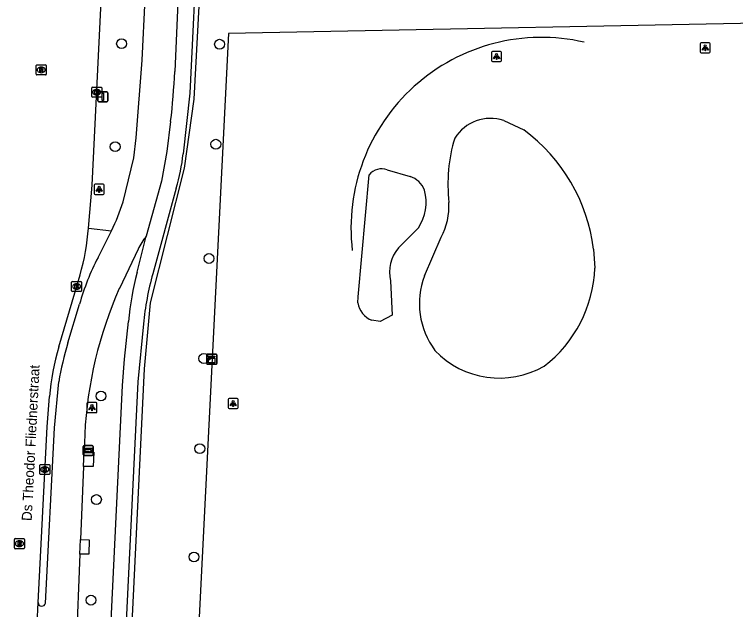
# Model space of a CAD drawing. Extents: x 161761 to 162722, y 384793 to 385405.
# Drawn here: x 162129 to 162200.7, y 385280.9 to 385340.1 of the extents above; entities that cross this region are included whole.
import ezdxf

# ---------------------------------------------------------------- set-up
doc = ezdxf.new("R2010")
doc.units = 0
for name, color, linetype in [('IMGEO_Berm_groen', 7, 'Continuous'), ('IMGEO_Boom', 7, 'Continuous'), ('IMGEO_Fietspad_gesloten', 7, 'Continuous'), ('IMGEO_Groenvoorziening', 7, 'Continuous'), ('IMGEO_Hek', 7, 'Continuous'), ('IMGEO_Kast', 7, 'Continuous'), ('IMGEO_Kolk', 7, 'Continuous'), ('IMGEO_Lichtpunt', 7, 'Continuous'), ('IMGEO_Openbare_ruimte_label', 7, 'Continuous'), ('IMGEO_Rijbaan_lokaal_gesloten', 7, 'Continuous'), ('IMGEO_Rioolput', 7, 'Continuous'), ('IMGEO_Verkeersbordpaal', 7, 'Continuous'), ('IMGEO_Verkeerseiland_open', 7, 'Continuous'), ('IMGEO_Voetpad_open', 7, 'Continuous'), ('IMGEO_Wegwijzer', 7, 'Continuous')]:
    doc.layers.add(name, color=color, linetype=linetype)

msp = doc.modelspace()

# ---------------------------------------------------------------- linework, layer by layer
at = {"layer": 'IMGEO_Berm_groen'}
for points in [[(162135.902, 385296.656), (162136.872, 385296.597), (162136.811, 385295.159), (162135.843, 385295.176)], [(162135.553, 385287.905), (162136.417, 385287.87), (162136.38, 385286.457), (162135.496, 385286.459)]]:
    msp.add_lwpolyline(points, dxfattribs=at)
at = {"layer": 'IMGEO_Boom'}
for centre in [(162139.634, 385337.193), (162149.378, 385337.145), (162138.998, 385326.956), (162149.005, 385327.204), (162148.319, 385315.843), (162147.806, 385305.902), (162137.589, 385302.172), (162147.413, 385296.939), (162137.138, 385291.878), (162146.832, 385286.174), (162136.595, 385281.876)]:
    msp.add_circle(centre, 0.489, dxfattribs=at)
at = {"layer": 'IMGEO_Fietspad_gesloten'}
for points in [[(162139.783, 385321.485), (162140.845, 385325.839), (162141.092, 385327.83), (162141.672, 385335.573), (162142.271, 385347.778), (162142.207, 385350.248)], [(162145.726, 385349.837), (162145.502, 385347.426), (162144.918, 385334.435)], [(162144.509, 385329.468), (162144.145, 385326.47), (162143.594, 385323.536), (162142.089, 385318.047)], [(162137.294, 385315.952), (162138.638, 385318.607)], [(162141.277, 385316.771), (162139.414, 385312.866)], [(162134.299, 385307.45), (162135.45, 385311.302)], [(162132.066, 385281.578), (162132.954, 385298.991), (162133.395, 385303.575)], [(162135.97, 385298.369), (162135.902, 385296.656)], [(162135.843, 385295.176), (162135.902, 385296.656)], [(162135.843, 385295.176), (162135.553, 385287.905)], [(162135.496, 385286.459), (162135.553, 385287.905)], [(162135.496, 385286.459), (162135.129, 385277.251)]]:
    msp.add_lwpolyline(points, dxfattribs=at)
for centre, radius, start, end in [((162086.015, 385336.785), 58.95, 352.86997, 357.7154), ((162120.972, 385327.302), 19.69, 333.79389, 342.81627), ((162146.167, 385314.556), 5.368, 139.43026, 155.62736), ((162160.039, 385304.242), 25.582, 152.75806, 163.97943), ((162176.927, 385296.297), 41.01, 156.16908, 177.10328), ((162164.556, 385298.348), 31.596, 163.2582, 170.47843), ((162131.708, 385281.644), 0.364, 182.24351, 349.51758)]:
    msp.add_arc(centre, radius, start, end, dxfattribs=at)
at = {"layer": 'IMGEO_Groenvoorziening'}
for points in [[(162399.858, 385354.488), (162376.31, 385353.749), (162286.233, 385352.376), (162211.155, 385350.962), (162211.124, 385352.462), (162147.884, 385351.44), (162146.81, 385331.678), (162145.872, 385324.819), (162142.47, 385311.424), (162141.898, 385304.88), (162139.214, 385249.548), (162133.367, 385130.823)], [(162211.326, 385339.4), (162150.256, 385338.217), (162139.817, 385130.505)], [(162177.62, 385329.568), (162179.614, 385328.627)], [(162166.039, 385324.657), (162168.314, 385323.994)], [(162163.132, 385311.434), (162163.14, 385312.033), (162164.244, 385324.166)], [(162169.135, 385318.896), (162168.204, 385317.932), (162167.159, 385316.892)], [(162169.762, 385314.116), (162171.42, 385317.948)], [(162186.548, 385316.774), (162186.681, 385314.893)], [(162166.353, 385313.631), (162166.541, 385310.198), (162165.325, 385309.574), (162164.511, 385309.697)]]:
    msp.add_lwpolyline(points, dxfattribs=at)
for centre, radius, start, end in [((162176.335, 385325.512), 4.255, 72.4177, 147.3575), ((162169.351, 385314.668), 17.326, 6.98055, 53.67468), ((162187.898, 385323.224), 15.824, 163.16473, 186.54671), ((162165.487, 385323.15), 1.605, 69.87674, 140.71991), ((162167.673, 385321.911), 2.18, 19.15887, 72.89747), ((162165.473, 385321.395), 4.434, 325.69235, 16.12111), ((162165.152, 385321.133), 7.031, 333.06244, 2.33814), ((162170.132, 385314.427), 3.862, 140.34079, 191.89285), ((162173.828, 385315.364), 12.861, 307.35532, 357.89986), ((162176.954, 385311.336), 7.711, 158.86431, 216.85174), ((162165.394, 385311.814), 2.294, 189.53904, 247.35291), ((162177.201, 385312.79), 8.84, 223.44992, 300.07993)]:
    msp.add_arc(centre, radius, start, end, dxfattribs=at)
at = {"layer": 'IMGEO_Hek'}
msp.add_lwpolyline([(162147.884, 385351.44), (162146.81, 385331.678), (162145.872, 385324.819), (162142.47, 385311.424), (162141.898, 385304.88), (162139.214, 385249.548)], dxfattribs=at)
msp.add_arc((162181.402, 385318.855), 18.965, 77.1096, 186.69883, dxfattribs=at)
at = {"layer": 'IMGEO_Kast'}
for p, q in [((162148.172, 385306.327), (162149.013, 385306.327)), ((162149.013, 385306.327), (162148.172, 385306.327)), ((162148.097, 385305.402), (162148.097, 385306.243)), ((162148.097, 385306.243), (162148.097, 385305.402)), ((162149.097, 385306.252), (162149.097, 385305.411)), ((162149.097, 385305.411), (162149.097, 385306.252)), ((162149.022, 385305.327), (162148.181, 385305.327)), ((162148.181, 385305.327), (162149.022, 385305.327))]:
    msp.add_line(p, q, dxfattribs=at)
for points in [[(162148.292, 385306.117), (162148.892, 385306.117), (162148.892, 385306.032), (162148.292, 385306.032), (162148.292, 385306.117)], [(162148.292, 385305.942), (162148.892, 385305.942), (162148.892, 385305.453), (162148.292, 385305.453), (162148.292, 385305.942)]]:
    msp.add_lwpolyline(points, dxfattribs=at)
msp.add_circle((162148.376, 385305.791), 0.0377, dxfattribs=at)
for centre, start, end in [((162148.175, 385306.249), 92.4484, 184.28452), ((162148.175, 385306.249), 92.4484, 184.28452), ((162149.019, 385306.249), 2.4484, 94.28452), ((162149.019, 385306.249), 2.4484, 94.28452), ((162148.175, 385305.405), 182.4484, 274.28452), ((162148.175, 385305.405), 182.4484, 274.28452), ((162149.019, 385305.405), 272.4484, 4.28452), ((162149.019, 385305.405), 272.4484, 4.28452)]:
    msp.add_arc(centre, 0.0779, start, end, dxfattribs=at)
at = {"layer": 'IMGEO_Kolk'}
for p, q in [((162136.742, 385332.875), (162137.594, 385332.875)), ((162136.667, 385331.949), (162136.667, 385332.801)), ((162137.155, 385332.655), (162137.18, 385332.655)), ((162137.668, 385332.801), (162137.668, 385331.949)), ((162137.594, 385331.875), (162136.742, 385331.875)), ((162137.178, 385332.095), (162137.153, 385332.095)), ((162134.742, 385313.557), (162135.594, 385313.557)), ((162134.667, 385312.631), (162134.667, 385313.483)), ((162135.178, 385312.777), (162135.153, 385312.777)), ((162135.155, 385313.337), (162135.18, 385313.337)), ((162135.668, 385313.483), (162135.668, 385312.631)), ((162135.594, 385312.557), (162134.742, 385312.557)), ((162131.507, 385294.441), (162131.507, 385295.293)), ((162131.582, 385295.367), (162132.434, 385295.367)), ((162131.995, 385295.147), (162132.02, 385295.147)), ((162132.508, 385295.293), (162132.508, 385294.441)), ((162132.434, 385294.367), (162131.582, 385294.367)), ((162132.018, 385294.587), (162131.993, 385294.587))]:
    msp.add_line(p, q, dxfattribs=at)
for points in [[(162136.742, 385332.875), (162137.594, 385332.875)], [(162136.667, 385331.949), (162136.667, 385332.801)], [(162136.988, 385332.575), (162137.111, 385332.575), (162137.111, 385332.424), (162137.241, 385332.575), (162137.405, 385332.575), (162137.259, 385332.424), (162137.412, 385332.175), (162137.26, 385332.175), (162137.175, 385332.339), (162137.111, 385332.272), (162137.111, 385332.175), (162136.988, 385332.175), (162136.988, 385332.575)], [(162137.668, 385332.801), (162137.668, 385331.949)], [(162137.594, 385331.875), (162136.742, 385331.875)], [(162134.742, 385313.557), (162135.594, 385313.557)], [(162134.667, 385312.631), (162134.667, 385313.483)], [(162134.988, 385313.257), (162135.111, 385313.257), (162135.111, 385313.106), (162135.241, 385313.257), (162135.405, 385313.257), (162135.259, 385313.106), (162135.412, 385312.857), (162135.26, 385312.857), (162135.175, 385313.021), (162135.111, 385312.954), (162135.111, 385312.857), (162134.988, 385312.857), (162134.988, 385313.257)], [(162135.668, 385313.483), (162135.668, 385312.631)], [(162135.594, 385312.557), (162134.742, 385312.557)], [(162131.507, 385294.441), (162131.507, 385295.293)], [(162131.582, 385295.367), (162132.434, 385295.367)], [(162131.828, 385295.067), (162131.951, 385295.067), (162131.951, 385294.916), (162132.081, 385295.067), (162132.245, 385295.067), (162132.099, 385294.916), (162132.252, 385294.667), (162132.1, 385294.667), (162132.015, 385294.831), (162131.951, 385294.764), (162131.951, 385294.667), (162131.828, 385294.667), (162131.828, 385295.067)], [(162132.508, 385295.293), (162132.508, 385294.441)], [(162132.434, 385294.367), (162131.582, 385294.367)]]:
    msp.add_lwpolyline(points, dxfattribs=at)
for centre, start, end in [((162136.744, 385332.799), 91.55205, 178.44795), ((162136.744, 385332.799), 91.55205, 178.44795), ((162137.592, 385332.799), 1.55205, 88.44795), ((162137.592, 385332.799), 1.55205, 88.44795), ((162136.744, 385331.951), 181.55205, 268.44795), ((162136.744, 385331.951), 181.55205, 268.44795), ((162137.592, 385331.951), 271.55205, 358.44795), ((162137.592, 385331.951), 271.55205, 358.44795), ((162134.744, 385313.481), 91.55205, 178.44795), ((162134.744, 385313.481), 91.55205, 178.44795), ((162135.592, 385313.481), 1.55205, 88.44795), ((162135.592, 385313.481), 1.55205, 88.44795), ((162134.744, 385312.633), 181.55205, 268.44795), ((162134.744, 385312.633), 181.55205, 268.44795), ((162135.592, 385312.633), 271.55205, 358.44795), ((162135.592, 385312.633), 271.55205, 358.44795), ((162131.584, 385295.291), 91.55205, 178.44795), ((162131.584, 385295.291), 91.55205, 178.44795), ((162132.432, 385295.291), 1.55205, 88.44795), ((162132.432, 385295.291), 1.55205, 88.44795), ((162131.584, 385294.443), 181.55205, 268.44795), ((162131.584, 385294.443), 181.55205, 268.44795), ((162132.432, 385294.443), 271.55205, 358.44795), ((162132.432, 385294.443), 271.55205, 358.44795)]:
    msp.add_arc(centre, 0.0765, start, end, dxfattribs=at)
for centre, major_axis, ratio, start_param, end_param in [((162137.154, 385332.375), (-0.387, 0.002), 0.722429, 4.712389, 7.853982), ((162137.179, 385332.375), (-0.39, 0.002), 0.717154, 1.570796, 4.712389), ((162135.154, 385313.057), (-0.387, 0.002), 0.722429, 4.712389, 7.853982), ((162135.179, 385313.057), (-0.39, 0.002), 0.717154, 1.570796, 4.712389), ((162131.994, 385294.867), (-0.387, 0.002), 0.722429, 4.712389, 7.853982), ((162132.019, 385294.867), (-0.39, 0.002), 0.717154, 1.570796, 4.712389)]:
    msp.add_ellipse(centre, major_axis=major_axis, ratio=ratio, start_param=start_param, end_param=end_param, dxfattribs=at)
at = {"layer": 'IMGEO_Lichtpunt'}
for p, q in [((162197.156, 385337.195), (162197.156, 385336.388)), ((162197.156, 385337.195), (162197.156, 385336.388)), ((162198.058, 385337.29), (162197.25, 385337.29)), ((162198.058, 385337.29), (162197.25, 385337.29)), ((162198.152, 385336.388), (162198.152, 385337.195)), ((162198.152, 385336.388), (162198.152, 385337.195)), ((162176.413, 385336.327), (162176.413, 385335.52)), ((162176.413, 385336.327), (162176.413, 385335.52)), ((162177.315, 385336.422), (162176.507, 385336.422)), ((162177.315, 385336.422), (162176.507, 385336.422)), ((162177.409, 385335.52), (162177.409, 385336.327)), ((162177.409, 385335.52), (162177.409, 385336.327)), ((162197.25, 385336.294), (162198.058, 385336.294)), ((162197.25, 385336.294), (162198.058, 385336.294)), ((162176.507, 385335.426), (162177.315, 385335.426)), ((162176.507, 385335.426), (162177.315, 385335.426)), ((162136.909, 385323.121), (162136.909, 385322.314)), ((162136.909, 385323.121), (162136.909, 385322.314)), ((162137.811, 385323.216), (162137.003, 385323.216)), ((162137.811, 385323.216), (162137.003, 385323.216)), ((162137.905, 385322.314), (162137.905, 385323.121)), ((162137.905, 385322.314), (162137.905, 385323.121)), ((162137.003, 385322.22), (162137.811, 385322.22)), ((162137.003, 385322.22), (162137.811, 385322.22)), ((162136.194, 385301.419), (162136.194, 385300.612)), ((162136.194, 385301.419), (162136.194, 385300.612)), ((162137.096, 385301.514), (162136.288, 385301.514)), ((162137.096, 385301.514), (162136.288, 385301.514)), ((162137.19, 385300.612), (162137.19, 385301.419)), ((162137.19, 385300.612), (162137.19, 385301.419)), ((162150.227, 385301.837), (162150.227, 385301.03)), ((162150.227, 385301.837), (162150.227, 385301.03)), ((162151.129, 385301.932), (162150.321, 385301.932)), ((162151.129, 385301.932), (162150.321, 385301.932)), ((162151.223, 385301.03), (162151.223, 385301.837)), ((162151.223, 385301.03), (162151.223, 385301.837)), ((162150.321, 385300.936), (162151.129, 385300.936)), ((162150.321, 385300.936), (162151.129, 385300.936)), ((162136.288, 385300.518), (162137.096, 385300.518)), ((162136.288, 385300.518), (162137.096, 385300.518))]:
    msp.add_line(p, q, dxfattribs=at)
for points in [[(162197.53, 385336.859), (162197.569, 385336.831), (162197.381, 385336.569), (162197.343, 385336.596), (162197.53, 385336.859)], [(162197.632, 385336.811), (162197.679, 385336.811), (162197.679, 385336.489), (162197.632, 385336.489), (162197.632, 385336.811)], [(162197.742, 385336.831), (162197.78, 385336.858), (162197.967, 385336.596), (162197.928, 385336.568), (162197.742, 385336.831)], [(162176.787, 385335.991), (162176.826, 385335.963), (162176.638, 385335.701), (162176.6, 385335.728), (162176.787, 385335.991)], [(162176.889, 385335.943), (162176.936, 385335.943), (162176.936, 385335.621), (162176.889, 385335.621), (162176.889, 385335.943)], [(162176.999, 385335.963), (162177.037, 385335.99), (162177.224, 385335.728), (162177.185, 385335.7), (162176.999, 385335.963)], [(162137.283, 385322.785), (162137.322, 385322.757), (162137.134, 385322.495), (162137.096, 385322.522), (162137.283, 385322.785)], [(162137.385, 385322.737), (162137.432, 385322.737), (162137.432, 385322.415), (162137.385, 385322.415), (162137.385, 385322.737)], [(162137.495, 385322.757), (162137.533, 385322.784), (162137.72, 385322.522), (162137.681, 385322.494), (162137.495, 385322.757)], [(162150.601, 385301.501), (162150.64, 385301.473), (162150.452, 385301.211), (162150.414, 385301.238), (162150.601, 385301.501)], [(162150.703, 385301.453), (162150.75, 385301.453), (162150.75, 385301.131), (162150.703, 385301.131), (162150.703, 385301.453)], [(162150.813, 385301.473), (162150.851, 385301.5), (162151.038, 385301.238), (162150.999, 385301.21), (162150.813, 385301.473)], [(162136.568, 385301.083), (162136.607, 385301.055), (162136.419, 385300.793), (162136.381, 385300.82), (162136.568, 385301.083)], [(162136.67, 385301.035), (162136.717, 385301.035), (162136.717, 385300.713), (162136.67, 385300.713), (162136.67, 385301.035)], [(162136.78, 385301.055), (162136.818, 385301.082), (162137.005, 385300.82), (162136.966, 385300.792), (162136.78, 385301.055)]]:
    msp.add_lwpolyline(points, dxfattribs=at)
for centre in [(162197.655, 385336.993), (162176.912, 385336.125), (162137.408, 385322.919), (162136.693, 385301.217), (162150.726, 385301.635)]:
    msp.add_circle(centre, 0.0994, dxfattribs=at)
for centre, start, end in [((162197.25, 385337.195), 90, 180), ((162197.25, 385337.195), 90, 180), ((162198.058, 385337.195), 0, 90), ((162198.058, 385337.195), 0, 90), ((162176.507, 385336.327), 90, 180), ((162176.507, 385336.327), 90, 180), ((162177.315, 385336.327), 0, 90), ((162177.315, 385336.327), 0, 90), ((162197.25, 385336.388), 180, 270), ((162197.25, 385336.388), 180, 270), ((162198.058, 385336.388), 270, 0), ((162198.058, 385336.388), 270, 360), ((162176.507, 385335.52), 180, 270), ((162176.507, 385335.52), 180, 270), ((162177.315, 385335.52), 270, 0), ((162177.315, 385335.52), 270, 360), ((162137.003, 385323.121), 90, 180), ((162137.003, 385323.121), 90, 180), ((162137.811, 385323.121), 0, 90), ((162137.811, 385323.121), 0, 90), ((162137.003, 385322.314), 180, 270), ((162137.003, 385322.314), 180, 270), ((162137.811, 385322.314), 270, 0), ((162137.811, 385322.314), 270, 360), ((162136.288, 385301.419), 90, 180), ((162136.288, 385301.419), 90, 180), ((162137.096, 385301.419), 0, 90), ((162137.096, 385301.419), 0, 90), ((162150.321, 385301.837), 90, 180), ((162150.321, 385301.837), 90, 180), ((162151.129, 385301.837), 0, 90), ((162151.129, 385301.837), 0, 90), ((162136.288, 385300.612), 180, 270), ((162136.288, 385300.612), 180, 270), ((162137.096, 385300.612), 270, 0), ((162137.096, 385300.612), 270, 360), ((162150.321, 385301.03), 180, 270), ((162150.321, 385301.03), 180, 270), ((162151.129, 385301.03), 270, 0), ((162151.129, 385301.03), 270, 360)]:
    msp.add_arc(centre, 0.0946, start, end, dxfattribs=at)
at = {"layer": 'IMGEO_Rijbaan_lokaal_gesloten'}
for points in [[(162136.346, 385318.869), (162136.706, 385323.145), (162138.078, 385350.894), (162138.352, 385356.061)], [(162133.404, 385307.058), (162135.513, 385314.217)], [(162131.344, 385281.63), (162132.238, 385299.116), (162132.459, 385302.12)], [(162131.151, 385277.397), (162131.344, 385281.63)]]:
    msp.add_lwpolyline(points, dxfattribs=at)
for centre, radius, start, end in [((162112.773, 385320.69), 23.644, 344.11222, 355.58387), ((162157.345, 385299.917), 24.983, 163.39122, 174.94103)]:
    msp.add_arc(centre, radius, start, end, dxfattribs=at)
at = {"layer": 'IMGEO_Rioolput'}
for p, q in [((162131.148, 385334.169), (162131.148, 385335.021)), ((162131.223, 385335.095), (162132.075, 385335.095)), ((162132.149, 385335.021), (162132.149, 385334.169)), ((162131.659, 385334.315), (162131.634, 385334.315)), ((162131.636, 385334.875), (162131.661, 385334.875)), ((162132.075, 385334.095), (162131.223, 385334.095)), ((162128.985, 385287.067), (162128.985, 385287.919)), ((162129.06, 385287.993), (162129.912, 385287.993)), ((162129.473, 385287.773), (162129.498, 385287.773)), ((162129.986, 385287.919), (162129.986, 385287.067)), ((162129.912, 385286.993), (162129.06, 385286.993)), ((162129.496, 385287.213), (162129.471, 385287.213))]:
    msp.add_line(p, q, dxfattribs=at)
for points in [[(162131.148, 385334.169), (162131.148, 385335.021)], [(162131.223, 385335.095), (162132.075, 385335.095)], [(162132.149, 385335.021), (162132.149, 385334.169)], [(162131.737, 385334.793), (162131.485, 385334.795), (162131.485, 385334.395)], [(162131.485, 385334.395), (162131.609, 385334.395), (162131.609, 385334.557), (162131.62, 385334.557)], [(162131.663, 385334.714), (162131.609, 385334.714), (162131.609, 385334.633)], [(162131.609, 385334.633), (162131.661, 385334.633)], [(162131.667, 385334.528), (162131.738, 385334.395), (162131.878, 385334.395), (162131.813, 385334.521)], [(162132.075, 385334.095), (162131.223, 385334.095)], [(162128.985, 385287.067), (162128.985, 385287.919)], [(162129.06, 385287.993), (162129.912, 385287.993)], [(162129.574, 385287.691), (162129.322, 385287.693), (162129.322, 385287.293)], [(162129.986, 385287.919), (162129.986, 385287.067)], [(162129.912, 385286.993), (162129.06, 385286.993)], [(162129.322, 385287.293), (162129.446, 385287.293), (162129.446, 385287.455), (162129.457, 385287.455)], [(162129.5, 385287.612), (162129.446, 385287.612), (162129.446, 385287.531)], [(162129.446, 385287.531), (162129.498, 385287.531)], [(162129.504, 385287.426), (162129.575, 385287.293), (162129.715, 385287.293), (162129.65, 385287.419)]]:
    msp.add_lwpolyline(points, dxfattribs=at)
for centre, radius, start, end in [((162131.225, 385335.019), 0.0765, 91.55205, 178.44795), ((162131.225, 385335.019), 0.0765, 91.55205, 178.44795), ((162132.073, 385335.019), 0.0765, 1.55205, 88.44795), ((162132.073, 385335.019), 0.0765, 1.55205, 88.44795), ((162131.619, 385334.504), 0.0533, 26.02933, 88.69889), ((162131.645, 385334.822), 0.19, 274.7715, 282.96867), ((162131.669, 385334.618), 0.0964, 77.00612, 93.18647), ((162131.683, 385334.675), 0.0378, 276.66336, 79.67722), ((162131.736, 385334.683), 0.109, 350.36119, 89.41601), ((162131.734, 385334.683), 0.112, 277.58423, 350.98172), ((162131.718, 385334.468), 0.108, 29.51342, 73.79051), ((162131.225, 385334.171), 0.0765, 181.55205, 268.44795), ((162131.225, 385334.171), 0.0765, 181.55205, 268.44795), ((162132.073, 385334.171), 0.0765, 271.55205, 358.44795), ((162132.073, 385334.171), 0.0765, 271.55205, 358.44795), ((162129.062, 385287.917), 0.0765, 91.55205, 178.44795), ((162129.062, 385287.917), 0.0765, 91.55205, 178.44795), ((162129.573, 385287.581), 0.109, 350.36119, 89.41601), ((162129.91, 385287.917), 0.0765, 1.55205, 88.44795), ((162129.91, 385287.917), 0.0765, 1.55205, 88.44795), ((162129.062, 385287.069), 0.0765, 181.55205, 268.44795), ((162129.062, 385287.069), 0.0765, 181.55205, 268.44795), ((162129.456, 385287.402), 0.0533, 26.02933, 88.69889), ((162129.482, 385287.72), 0.19, 274.7715, 282.96867), ((162129.506, 385287.516), 0.0964, 77.00612, 93.18647), ((162129.52, 385287.573), 0.0378, 276.66336, 79.67722), ((162129.571, 385287.581), 0.112, 277.58423, 350.98172), ((162129.555, 385287.366), 0.108, 29.51342, 73.79051), ((162129.91, 385287.069), 0.0765, 271.55205, 358.44795), ((162129.91, 385287.069), 0.0765, 271.55205, 358.44795)]:
    msp.add_arc(centre, radius, start, end, dxfattribs=at)
for centre, major_axis, ratio, start_param, end_param in [((162131.635, 385334.595), (-0.387, 0.002), 0.722429, 4.712389, 7.853982), ((162131.66, 385334.595), (-0.39, 0.002), 0.717154, 1.570796, 4.712389), ((162129.472, 385287.493), (-0.387, 0.002), 0.722429, 4.712389, 7.853982), ((162129.497, 385287.493), (-0.39, 0.002), 0.717154, 1.570796, 4.712389)]:
    msp.add_ellipse(centre, major_axis=major_axis, ratio=ratio, start_param=start_param, end_param=end_param, dxfattribs=at)
at = {"layer": 'IMGEO_Verkeersbordpaal'}
for p, q in [((162137.275, 385331.512), (162137.275, 385332.312)), ((162137.275, 385332.312), (162137.275, 385331.512)), ((162137.375, 385332.412), (162138.165, 385332.412)), ((162138.165, 385332.412), (162137.375, 385332.412)), ((162138.265, 385332.312), (162138.265, 385331.512)), ((162138.265, 385331.512), (162138.265, 385332.312)), ((162138.165, 385331.412), (162137.375, 385331.412)), ((162137.375, 385331.412), (162138.165, 385331.412))]:
    msp.add_line(p, q, dxfattribs=at)
msp.add_lwpolyline([(162137.695, 385332.287), (162137.845, 385332.287), (162137.845, 385331.537), (162137.695, 385331.537), (162137.695, 385332.287)], dxfattribs=at)
for centre, start, end in [((162137.375, 385332.312), 90, 180), ((162137.375, 385332.312), 90, 180), ((162138.165, 385332.312), 0, 90), ((162138.165, 385332.312), 360, 90), ((162137.375, 385331.512), 180, 270), ((162137.375, 385331.512), 180, 270), ((162138.165, 385331.512), 270, 0), ((162138.165, 385331.512), 270, 0)]:
    msp.add_arc(centre, 0.1, start, end, dxfattribs=at)
at = {"layer": 'IMGEO_Verkeerseiland_open'}
msp.add_lwpolyline([(162136.346, 385318.869), (162138.638, 385318.607)], dxfattribs=at)
at = {"layer": 'IMGEO_Voetpad_open'}
for points in [[(162147.19, 385348.002), (162146.419, 385332.292), (162145.754, 385326.254)], [(162145.067, 385322.828), (162142.737, 385314.33)], [(162141.17, 385314.469), (162142.089, 385318.047)], [(162134.787, 385270.387), (162138.123, 385270.221), (162139.724, 385303.205), (162139.916, 385305.842), (162140.326, 385309.592)], [(162141.818, 385309.344), (162141.256, 385303.578), (162138.882, 385254.554), (162134.904, 385254.707)]]:
    msp.add_lwpolyline(points, dxfattribs=at)
for centre, radius, start, end in [((162127.687, 385328.095), 18.161, 343.14065, 354.1816), ((162172.317, 385306.567), 32.134, 165.76484, 174.59875), ((162169.832, 385306.758), 28.133, 164.38692, 174.72643)]:
    msp.add_arc(centre, radius, start, end, dxfattribs=at)
at = {"layer": 'IMGEO_Wegwijzer'}
for p, q in [((162135.832, 385296.348), (162135.832, 385297.148)), ((162135.832, 385297.148), (162135.832, 385296.348)), ((162135.932, 385297.248), (162136.722, 385297.248)), ((162136.722, 385297.248), (162135.932, 385297.248)), ((162136.822, 385297.148), (162136.822, 385296.348)), ((162136.822, 385296.348), (162136.822, 385297.148)), ((162136.722, 385296.248), (162135.932, 385296.248)), ((162135.932, 385296.248), (162136.722, 385296.248))]:
    msp.add_line(p, q, dxfattribs=at)
for points in [[(162135.933, 385296.98), (162136.721, 385296.98), (162136.721, 385296.516), (162135.933, 385296.516), (162135.933, 385296.98)], [(162135.998, 385296.832), (162135.998, 385296.748), (162135.998, 385296.664), (162136.409, 385296.664), (162136.409, 385296.581), (162136.656, 385296.748), (162136.409, 385296.915), (162136.409, 385296.832), (162135.998, 385296.832)]]:
    msp.add_lwpolyline(points, dxfattribs=at)
for centre, start, end in [((162135.932, 385297.148), 90, 180), ((162135.932, 385297.148), 90, 180), ((162136.722, 385297.148), 0, 90), ((162136.722, 385297.148), 360, 90), ((162135.932, 385296.348), 180, 270), ((162135.932, 385296.348), 180, 270), ((162136.722, 385296.348), 270, 0), ((162136.722, 385296.348), 270, 0)]:
    msp.add_arc(centre, 0.1, start, end, dxfattribs=at)

# ---------------------------------------------------------------- texts
at = {"layer": 'IMGEO_Openbare_ruimte_label'}
msp.add_text('Ds Theodor Fliednerstraat', height=1, rotation=87.07753, dxfattribs=at).set_placement((162130.7, 385289.727))

doc.saveas('drawing.dxf')
